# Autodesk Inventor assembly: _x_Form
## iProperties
Created: 2005-11
Part Number: _x_Form
Document SubType Name: Assembly
Designer: IMA/Frank
Manufacturer: Standard
Standards Organization: Custom
Author: IMA/Frank
